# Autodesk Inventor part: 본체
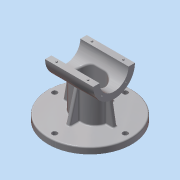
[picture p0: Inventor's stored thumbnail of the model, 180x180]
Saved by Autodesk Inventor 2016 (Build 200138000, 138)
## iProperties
Created: 2015-12
Part Number: 본체
Material: 알루미늄 6061
Document SubType Name: Modeling
Designer: mduedu
Density: 2.71 g/cm^3
Mass: 616.11 g
Surface Area: 573.393 cm^2
Volume: 227.347 cm^3
Appearance: 알루미늄 - 평지
Author: mduedu
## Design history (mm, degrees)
sketch "스케치1"
  geometry: C1 r 65 at (0, 0); 1 further point
  constraints: 1 centre point, 1 coincident
  dimensions: "d124" = 130 diameter of C1
extrude "돌출1" new body sketch "스케치1" distance "d3" = 10; taper "d4" = 0 deg
sketch "스케치2"
  geometry: C1 r 32.5 at (80, 0); 1 further point
  constraints: 1 centre point, 1 horizontal alignment
  dimensions: "d5" = 65 diameter of C1; "d125" = 80 distance of C1.centre point (0, 0)
extrude "돌출2" join sketch "스케치2" stored distance "d7" = 75; taper "d8" = 0 deg
sketch "스케치3"
  geometry: L1 (-27.5, -20)-(27.5, -20); L2 (27.5, -20)-(27.5, 20); L3 (27.5, 20)-(-27.5, 20); L4 (-27.5, 20)-(-27.5, -20); L5 (-27.5, -20)-(27.5, 20); L6 (27.5, -20)-(-27.5, 20); 1 further point
  constraints: 12 end point, 2 midpoint, 2 parallel, 1 horizontal, 1 perpendicular
  dimensions: "d9" = 55 distance of L2.end L3.end; "d11" = 40 distance of L1.end L2.end
extrude "돌출3" new body sketch "스케치3" stored distance "d12" = 75; taper "d13" = 0 deg
fillet "모깎기1"
fillet "모깎기2"
feature "결합1"
  node "솔리드2"
sketch "스케치4"
  geometry: L1 (-37.5, 47.5)-(37.5, 47.5) reference; L2 (32.5, 47.5)-(39.112, 10); L3 (37.5, 47.5)-(37.5, 112.5) reference; L4 (65, 10)-(-65, 10) reference; 1 further point
  constraints: 2 end point, 2 point on line
  dimensions: "d15" = 5 distance from line of L2.start L3; "d126" = 80 deg angle of L2 L1
sketch "스케치5"
  geometry: L1 (10, 35)-(56.569, 22.522); L2 (10, -65)-(10, 65) reference; L3 (10, 20)-(54.383, 20) reference; A1 r 32.5 centre (80, 0) between (56.569, 22.522) and (54.383, 20) reference; 1 further point
  constraints: 2 end point, 1 point on circle, 1 point on line
  dimensions: "d127" = 75 deg angle of L1 L2; "d128" = 15 distance of L1.start L3.start
feature "리브1" dims "d19" = 1, "d20" = 6, "d21" = 0, "d22" = 0, "d23" = 1, "d24" = 1
feature "리브2" dims "d25" = 1, "d26" = 6, "d27" = 0, "d28" = 0, "d29" = 1, "d30" = 1
fillet "모깎기4" dims "d31" = 2
fillet "모깎기5" dims "d32" = 2
fillet "모깎기6" dims "d33" = 2
fillet "모깎기7" dims "d41" = 2
hole "구멍2" diameter "d44" = 45; stored, may be unused: countersink angle "d48" = 90 deg, drill point angle "d50" = 118 deg; dims "d42" = 10, "d43" = 10, "d45" = 6, "d46" = 4, "d47" = 2, "d49" = 8
sketch "스케치7" dims "d52" = 26.5
  geometry: L1 (0, 0)-(32.5, 0); L2 (0, 0)-(22.981, 22.981); A1 r 32.5 centre (0, 0) between (32.5, 0) and (22.981, 22.981) reference; 3 further points
  constraints: 4 end point, 2 point on circle, 1 coincident, 1 horizontal, 1 point on line, 3 other
  dimensions: "d51" = 45 deg angle of L2 L1
hole "구멍3" sketch "스케치7" at (18.738, 18.738) diameter "d54" = 2.459; stored, may be unused: countersink angle "d58" = 90 deg, drill point angle "d60" = 118 deg; dims "d55" = 8, "d56" = 4, "d57" = 2, "d59" = 10
sketch "스케치9"
  geometry: L1 (-75, 82.5)-(75, 82.5); L2 (75, 82.5)-(75, 0); L3 (75, 0)-(-75, 0); L4 (-75, 0)-(-75, 82.5); C1 r 32.5 at (0, 0) reference; 2 further points
  constraints: 8 end point, 2 parallel, 1 coincident, 1 horizontal, 1 midpoint, 1 perpendicular
  dimensions: "d71" = 50 distance edge to line of C1 L1; "d116" = 150 distance between parallel lines of L2 L4
extrude "돌출5" cut sketch "스케치9" stored distance "d73" = 0; taper "d74" = 0 deg
node "작업 평면1"
sketch "스케치10"
  geometry: L1 (-7.5, 15)-(7.5, 15); L2 (-7.5, -15)-(7.5, -15); A1 r 20 centre (-7.5, 0) between (-7.5, 20) and (-26.977, 4.545) reference; A2 r 20 centre (7.5, 0) between (26.977, 4.545) and (7.5, 20) reference; A3 r 15 centre (-7.5, 0) between (-7.5, 15) and (-7.5, -15); A4 r 15 centre (7.5, 0) between (7.5, -15) and (7.5, 15); 1 further point
  constraints: 7 point on circle, 4 end point, 4 tangent, 3 point on line, 2 centre point, 2 coincident, 1 horizontal
  dimensions: "d77" = 5 radial gap between concentric circles of A3 A1
extrude "돌출6" cut sketch "스케치10" stored distance "d78" = 50; taper "d79" = 0 deg
fillet "모깎기10" dims "d80" = 3
sketch "스케치11"
  geometry: 2 further points
  constraints: 1 coincident
hole "구멍4" sketch "스케치11" at (0, 0) diameter "d81" = 12; stored, may be unused: countersink angle "d85" = 90 deg, drill point angle "d87" = 118 deg; dims "d82" = 8, "d83" = 40, "d84" = 10, "d86" = 10
sketch "스케치12"
  geometry: C1 r 10 at (0, 0); 1 further point
  constraints: 1 centre point, 1 coincident
  dimensions: "d88" = 20 diameter of C1
extrude "돌출7" cut sketch "스케치12" distance "d89" = 5; taper "d90" = 0 deg
chamfer "모따기1" distance "d91" = 1; stored, may be unused: second distance "d92" = 2, angle "d93" = 45 deg
fillet "모깎기11" dims "d94" = 0.5
fillet "모깎기12" dims "d115" = 0.3
sketch "스케치15"
  geometry: L1 (-75, 55)-(-75, 65) reference; L2 (0, 65)-(0, 55) reference; L3 (-75, 60)-(0, 60); C1 r 1.5 at (-62, 60); 1 further point
  constraints: 2 end point, 2 midpoint, 1 centre point, 1 point on line
  dimensions: "d117" = 3 diameter of C1; "d118" = 13 distance from line of C1.centre L1
extrude "돌출8" join sketch "스케치15" distance "d119" = 1.8; taper "d120" = 0 deg
chamfer "모따기2" distance "d121" = 0.5; stored, may be unused: second distance "d122" = 2, angle "d123" = 45 deg
sketch "스케치18" dims "d141" = 110
  geometry: C1 r 63 at (0, 0) reference; 2 further points
  constraints: 2 vertical alignment, 1 coincident, 2 other
hole "구멍8" sketch "스케치18" at (0, 55) diameter "d142" = 8; stored, may be unused: countersink angle "d146" = 90 deg, drill point angle "d148" = 118 deg; dims "d143" = 6, "d144" = 4, "d145" = 2, "d147" = 8
node "솔리드1"
mirror "대칭1"
mirror "대칭2"
pattern_circular "원형 패턴1" dims angle "d62" = 360 deg
mirror "대칭3"
mirror "대칭5"
mirror "대칭6"
pattern_circular "원형 패턴2" dims angle "d150" = 360 deg
mirror "대칭7"
